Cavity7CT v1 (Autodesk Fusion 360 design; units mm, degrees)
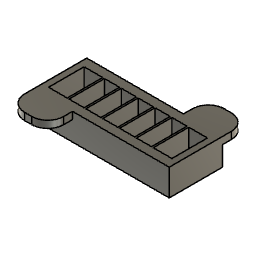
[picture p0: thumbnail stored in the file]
sketch "Sketch1" plane through (0, 0, 0) normal (0, 0, 1) x axis (1, 0, 0)
  line L1 (10.5, 0) -> (0, 0)
  line L2 (10.5, 20) -> (10.5, 0)
  line L3 (0, 20) -> (10.5, 20)
  line L4 (0, 0) -> (0, 20)
  line L5 (20, 0) -> (11.5, 0)
  line L6 (20, 20) -> (20, 0)
  line L7 (11.5, 20) -> (20, 20)
  line L8 (11.5, 0) -> (11.5, 20)
  line L9 (29.5, 0) -> (21, 0)
  line L10 (29.5, 20) -> (29.5, 0)
  line L11 (21, 20) -> (29.5, 20)
  line L12 (21, 0) -> (21, 20)
  line L13 (39, 0) -> (30.5, 0)
  line L14 (39, 20) -> (39, 0)
  line L15 (30.5, 20) -> (39, 20)
  line L16 (30.5, 0) -> (30.5, 20)
  line L17 (48.5, 0) -> (40, 0)
  line L18 (48.5, 20) -> (48.5, 0)
  line L19 (40, 20) -> (48.5, 20)
  line L20 (40, 0) -> (40, 20)
  line L21 (58, 0) -> (49.5, 0)
  line L22 (58, 20) -> (58, 0)
  line L23 (49.5, 20) -> (58, 20)
  line L24 (49.5, 0) -> (49.5, 20)
  line L25 (69.5, 0) -> (59, 0)
  line L26 (69.5, 20) -> (69.5, 0)
  line L27 (59, 20) -> (69.5, 20)
  line L28 (59, 0) -> (59, 20)
  line L29 (73, -5) -> (-3.5, -5)
  line L30 (73, 25) -> (73, -5)
  line L31 (-3.5, 25) -> (73, 25)
  line L32 (-3.5, -5) -> (-3.5, 25)
  point P1 (0, 0)
  point P2 (0, 0)
  point P3 (10.5, 0)
  point P5 (0, 20)
  point P6 (11.5, 0)
  point P7 (20, 0)
  point P9 (11.5, 20)
  point P10 (21, 0)
  point P11 (29.5, 0)
  point P13 (21, 20)
  point P14 (30.5, 0)
  point P15 (39, 0)
  point P17 (30.5, 20)
  point P18 (40, 0)
  point P19 (48.5, 0)
  point P21 (40, 20)
  point P22 (49.5, 0)
  point P23 (58, 0)
  point P25 (49.5, 20)
  point P26 (59, 0)
  point P27 (69.5, 0)
  point P29 (59, 20)
  horizontal L1
  vertical L2
  horizontal L3
  vertical L4
  coincident P1 P2
  horizontal L5
  vertical L6
  horizontal L7
  vertical L8
  horizontal L9
  vertical L10
  horizontal L11
  vertical L12
  horizontal L13
  vertical L14
  horizontal L15
  vertical L16
  horizontal L17
  vertical L18
  horizontal L19
  vertical L20
  horizontal L21
  vertical L22
  horizontal L23
  vertical L24
  horizontal L25
  vertical L26
  horizontal L27
  vertical L28
  horizontal L29
  vertical L30
  horizontal L31
  vertical L32
  dimension "d1" distance P2 P3 = 10.5
  dimension "d2" distance P2 P5 = 20
  dimension "d3" distance P6 P7 = 8.5
  dimension "d4" distance P6 P9 = 20
  dimension "d5" distance P10 P11 = 8.5
  dimension "d6" distance P10 P13 = 20
  dimension "d7" distance P14 P15 = 8.5
  dimension "d8" distance P14 P17 = 20
  dimension "d9" distance P18 P19 = 8.5
  dimension "d10" distance P18 P21 = 20
  dimension "d11" distance P22 P23 = 8.5
  dimension "d12" distance P22 P25 = 20
  dimension "d13" distance P26 P27 = 10.5
  dimension "d14" distance P26 P29 = 20
  dimension "d15" distance L2 L8 = 1
  dimension "d16" distance L6 L12 = 1
  dimension "d17" distance L10 L16 = 1
  dimension "d18" distance L14 L20 = 1
  dimension "d19" distance L18 L24 = 1
  dimension "d20" distance L22 L28 = 1
  dimension "d21" distance L26 L30 = 3.5
  dimension "d22" distance L23 L31 = 5
  dimension "d23" distance L25 L29 = 5
  dimension "d24" distance L4 L32 = 3.5
extrude "Extrude1" new body sketch "Sketch1" along normal blind 15
sketch "Sketch2" plane through (59, 0, 0) normal (1, 0, 0) x axis (0, 1, 0)
  line L1 (20, 0) -> (0, 0)
  line L2 (20, 15) -> (20, 0)
  line L3 (0, 15) -> (20, 15)
  line L4 (0, 0) -> (0, 15)
  line L5 (0, 0) -> (20, 0)
  line L6 (0, 3) -> (0, 0)
  line L7 (20, 3) -> (0, 3)
  line L8 (20, 0) -> (20, 3)
  point P3 (20, 0)
  point P6 (20, 0)
  point P7 (0, 0)
  point P9 (20, 3)
  horizontal L5
  vertical L6
  horizontal L7
  vertical L8
  coincident P3 P6
  dimension "d27" distance P6 P7 = 20
  dimension "d28" distance P6 P9 = 3
extrude "Extrude2" cut sketch "Sketch2" profile of L1 L2 L4 L5 L6 L7 L8 against normal blind 52
sketch "Sketch3" plane through (0, -5, 0) normal (0, -1, 0) x axis (1, 0, 0)
  line L1 (73, 0) -> (-3.5, 0)
  line L2 (73, 15) -> (73, 0)
  line L3 (-3.5, 15) -> (73, 15)
  line L4 (-3.5, 0) -> (-3.5, 15)
  line L5 (18.5, 15) -> (-3.5, 15)
  line L6 (18.5, 11) -> (18.5, 15)
  line L7 (-3.5, 11) -> (18.5, 11)
  line L8 (-3.5, 15) -> (-3.5, 11)
  point P5 (-3.5, 15)
  point P6 (-3.5, 15)
  point P7 (18.5, 15)
  horizontal L5
  vertical L6
  horizontal L7
  vertical L8
  coincident P5 P6
  dimension "d31" distance P6 P7 = 22
  dimension "d32" distance L5 L7 = 4
extrude "Extrude3" add sketch "Sketch3" profile of L3 L4 L5 L6 L7 L8 along normal blind 14
fillet "Fillet1" radius 9
sketch "Sketch4" plane through (0, 25, 0) normal (0, 1, 0) x axis (-1, 0, 0)
  line L1 (3.5, 0) -> (-73, 0)
  line L2 (3.5, 15) -> (3.5, 0)
  line L3 (-73, 15) -> (3.5, 15)
  line L4 (-73, 0) -> (-73, 15)
  line L5 (-51, 15) -> (-73, 15)
  line L6 (-51, 11) -> (-51, 15)
  line L7 (-73, 11) -> (-51, 11)
  line L8 (-73, 15) -> (-73, 11)
  point P5 (-73, 15)
  point P6 (-73, 15)
  point P7 (-51, 15)
  point P9 (-73, 11)
  horizontal L5
  vertical L6
  horizontal L7
  vertical L8
  coincident P5 P6
  dimension "d37" distance P6 P7 = 22
  dimension "d38" distance P6 P9 = 4
extrude "Extrude4" add sketch "Sketch4" profile of L3 L4 L5 L6 L7 L8 along normal blind 14
fillet "Fillet2" radius 9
